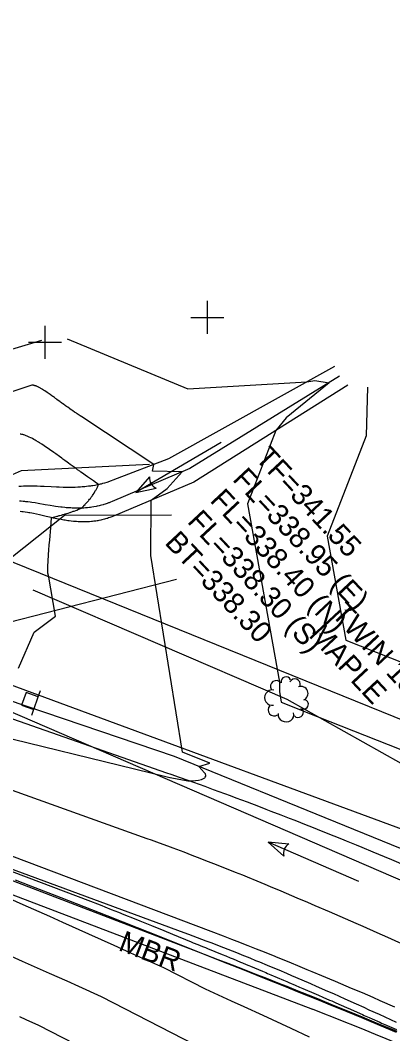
# Model space of a CAD drawing. Extents: x 487096 to 489566, y 221939 to 224454.
# Drawn here: x 488220.2 to 488276.8, y 223618.2 to 223772 of the extents above; entities that cross this region are included whole.
import ezdxf

# ---------------------------------------------------------------- set-up
doc = ezdxf.new("R2010")
doc.units = 0
for name, color, linetype in [('SV_BKLN_BKLN', 7, 'Continuous'), ('SV_DRAN_DRAN_TX', 7, 'Continuous'), ('SV_GDRL_GDRL_TX', 7, 'Continuous'), ('SV_GDRL_GR', 7, 'Continuous'), ('SV_MISC_MISC_TOPO', 7, 'Continuous'), ('SV_PIPE_CM_15', 7, 'Continuous'), ('SV_PIPE_FLOW', 7, 'Continuous'), ('SV_ROAD_BITRD', 7, 'Continuous'), ('SV_ROWL_HWYLOC', 7, 'Continuous'), ('SV_SIGN_SIGN', 7, 'Continuous'), ('SV_SURF_INDEX_CONTOUR', 7, 'Continuous'), ('SV_SURF_INTER_CONTOUR', 7, 'Continuous'), ('SV_SURF_SPOT', 7, 'Continuous'), ('SV_TRAF_PVMTL', 7, 'Continuous'), ('SV_TREE_TREELN', 7, 'Continuous'), ('SV_TREE_TREEVEG', 7, 'Continuous'), ('SV_TREE_TREEVEG_TX', 7, 'Continuous'), ('SV_UTOH_OVERHEAD_LINES', 7, 'Continuous'), ('SV_WATR_INWETF', 7, 'Continuous'), ('SV_WATR_STREAM', 7, 'Continuous')]:
    doc.layers.add(name, color=color, linetype=linetype)

msp = doc.modelspace()

# ---------------------------------------------------------------- linework, layer by layer
at = {"layer": 'SV_BKLN_BKLN'}
for points in [[(488268.72, 223718), (488246, 223704.02), (488234.18, 223698.97), (488233.93, 223698.86), (488233.76, 223698.8), (488233.65, 223698.76), (488233.43, 223698.68), (488233.26, 223698.62), (488233.15, 223698.58), (488232.93, 223698.51), (488232.82, 223698.48), (488232.59, 223698.42), (488232.37, 223698.36), (488232.22, 223698.32), (488231.93, 223698.26), (488231.76, 223698.22), (488231.43, 223698.16), (488231.1, 223698.11), (488230.88, 223698.08), (488230.74, 223698.06), (488230.45, 223698.03), (488230.12, 223698), (488229.9, 223697.99), (488229.76, 223697.98), (488229.47, 223697.97), (488229.25, 223697.97), (488229.11, 223697.97), (488228.82, 223697.97), (488228.68, 223697.97), (488228.39, 223697.98), (488228.11, 223697.99), (488227.92, 223698), (488227.55, 223698.02), (488227.23, 223698.05), (488227.02, 223698.07), (488226.61, 223698.11), (488226.4, 223698.14), (488225.99, 223698.19), (488225.58, 223698.25), (488225.31, 223698.29), (488224.78, 223698.37), (488224, 223698.5), (488222.97, 223698.68), (488222.48, 223698.76), (488221.99, 223698.83), (488221.75, 223698.87), (488221.39, 223698.92), (488221.07, 223698.95), (488220.92, 223698.97), (488220.69, 223698.99), (488220.35, 223699.02), (488220.13, 223699.03)], [(488277.34, 223618.4), (488274.85, 223619.44), (488273.18, 223620.14), (488272.07, 223620.59), (488269.85, 223621.51), (488267.35, 223622.53), (488265.69, 223623.21), (488262.35, 223624.56), (488260.68, 223625.24), (488257.34, 223626.58), (488253.99, 223627.92), (488251.76, 223628.81), (488247.3, 223630.58), (488241.13, 223633.03), (488238.05, 223634.25), (488233.41, 223636.07), (488228.78, 223637.89), (488226.46, 223638.8), (488221.82, 223640.61), (488219.5, 223641.51)]]:
    msp.add_lwpolyline(points, dxfattribs=at)
at = {"layer": 'SV_DRAN_DRAN_TX'}
msp.add_line((488243.95, 223687.13), (488198.45, 223675.49), dxfattribs=at)
at = {"layer": 'SV_GDRL_GR'}
msp.add_lwpolyline([(488277.44, 223618.52), (488276.61, 223618.87), (488274.95, 223619.56), (488273.28, 223620.25), (488272.18, 223620.71), (488269.95, 223621.63), (488267.45, 223622.65), (488265.78, 223623.33), (488264.67, 223623.77), (488262.43, 223624.67), (488260.76, 223625.34), (488259.64, 223625.78), (488257.4, 223626.66), (488256.28, 223627.1), (488254.04, 223627.98), (488251.8, 223628.85), (488250.3, 223629.43), (488247.3, 223630.58), (488176.7, 223657.65), (488168.14, 223658.69), (488156.25, 223662.12)], dxfattribs=at)
at = {"layer": 'SV_MISC_MISC_TOPO'}
msp.add_line((488247.47, 223631.33), (488247.47, 223631.33), dxfattribs=at)
at = {"layer": 'SV_PIPE_CM_15'}
msp.add_lwpolyline([(488383.93, 223595.7), (488200.04, 223675.13)], dxfattribs=at)
at = {"layer": 'SV_PIPE_FLOW'}
for p, q in [((488250.72, 223707.96), (488237.8, 223700.34)), ((488239.88, 223702.73), (488237.8, 223700.34)), ((488237.8, 223700.34), (488240.89, 223701)), ((488271.65, 223641.32), (488257.88, 223647.26)), ((488257.88, 223647.26), (488260.23, 223645.15)), ((488261.03, 223646.99), (488257.88, 223647.26))]:
    msp.add_line(p, q, dxfattribs=at)
for centre, start, end in [((488241.5, 223702.53), 172.9205, 248.1221), ((488261.82, 223645.56), 119.0376, 194.2393)]:
    msp.add_arc(centre, 1.64, start, end, dxfattribs=at)
at = {"layer": 'SV_ROAD_BITRD'}
for points in [[(488295.35, 223639.2), (488243.64, 223660.28), (488207.07, 223672.67)], [(488277.35, 223619.89), (488275.62, 223620.69), (488274.75, 223621.09), (488273.22, 223621.79), (488272.45, 223622.15), (488271.29, 223622.67), (488269.56, 223623.45), (488267.82, 223624.23), (488266.95, 223624.61), (488265.21, 223625.38), (488264.34, 223625.76), (488263.03, 223626.33), (488261.47, 223627), (488260.69, 223627.33), (488259.53, 223627.82), (488258.36, 223628.31), (488257.77, 223628.55), (488256.6, 223629.04), (488256.01, 223629.28), (488255.13, 223629.64), (488253.95, 223630.12), (488253.36, 223630.35), (488252.48, 223630.7), (488251.15, 223631.23), (488249.97, 223631.69), (488249.37, 223631.92), (488248.48, 223632.26), (488247.15, 223632.77), (488245.81, 223633.27), (488245.14, 223633.51), (488178.96, 223657.88)]]:
    msp.add_lwpolyline(points, dxfattribs=at)
at = {"layer": 'SV_ROWL_HWYLOC'}
for points in [[(487756.92, 223854.03), (487819.74, 223823.93), (487982.51, 223759.36), (488009.69, 223754.74), (488041.14, 223750.63), (488071.96, 223735.45), (488100.92, 223722.74), (488124.66, 223715.6), (488155.68, 223709.25), (488178.9, 223706.07), (488296.16, 223658.56), (488379.4, 223617.17), (488410.15, 223595.68), (488443.8, 223549.21), (488472.24, 223469.86), (488477.06, 223418.16), (488475.62, 223352.08), (488474.08, 223317.48), (488463.17, 223231.25), (488461.58, 223189.46)], [(487750.08, 223817.31), (487833.81, 223784.33), (487880.61, 223763.01), (487930.05, 223747.42), (487951.57, 223737.03), (487996.66, 223715.69), (488020.23, 223704.76), (488056.94, 223694.06), (488093.65, 223683.37), (488127.21, 223671.39), (488156.25, 223662.12), (488168.14, 223658.69), (488264.6, 223621.9)]]:
    msp.add_lwpolyline(points, dxfattribs=at)
msp.add_arc((488082.83, 223151.77), 504.05, 56.3623, 68.8615, dxfattribs=at)
at = {"layer": 'SV_SIGN_SIGN'}
for p, q in [((488222.97, 223669.31), (488223.31, 223670.28)), ((488221.98, 223666.53), (488222.31, 223667.45))]:
    msp.add_line(p, q, dxfattribs=at)
msp.add_lwpolyline([(488222.29, 223667.43), (488222.96, 223669.32), (488221.11, 223669.98), (488220.43, 223668.09)], close=True, dxfattribs=at)
at = {"layer": 'SV_SURF_INDEX_CONTOUR'}
msp.add_lwpolyline([(488196.14, 223642.96), (488198.31, 223642.06), (488207.61, 223634.91), (488209.83, 223633.95), (488211.3, 223633.31), (488212.27, 223632.89), (488214.2, 223632.04), (488216.34, 223631.1), (488217.75, 223630.47), (488220.54, 223629.23), (488221.91, 223628.62), (488224.63, 223627.4), (488227.31, 223626.2), (488229.06, 223625.41), (488232.53, 223623.85), (488250.32, 223614.68)], dxfattribs=at)
at = {"layer": 'SV_SURF_INTER_CONTOUR'}
for points in [[(488223.46, 223723.45), (488178.62, 223709.99), (488178.12, 223709.92), (488177.51, 223709.86), (488156.06, 223710.21), (488154.95, 223709.99), (488152.78, 223709.84), (488137.33, 223707.09), (488132.77, 223701.96), (488101.76, 223708.87)], [(488227.38, 223723.67), (488245.66, 223716.07), (488263.72, 223717.15), (488264.94, 223717.38), (488267.13, 223717.02), (488260.62, 223711.71), (488259.04, 223709.75), (488254.73, 223698.61), (488259.59, 223671.55), (488259.58, 223670.15), (488259.84, 223668.53), (488265.33, 223666.37), (488290.74, 223656.31)], [(488212.07, 223664.63), (488242.33, 223657.26), (488242.97, 223657.11), (488243, 223657.1), (488244.31, 223656.83), (488244.34, 223656.82), (488245.7, 223656.59), (488245.71, 223656.59), (488245.93, 223656.56), (488246.4, 223656.57), (488247.32, 223656.67), (488247.76, 223656.78), (488247.97, 223656.86), (488248.24, 223657.04), (488248.32, 223657.13), (488248.39, 223657.3), (488248.39, 223657.46), (488248.36, 223657.55), (488248.34, 223657.62), (488248.27, 223657.73), (488248.21, 223657.82), (488248.17, 223657.87), (488248.08, 223657.97), (488248.03, 223658.02), (488247.94, 223658.1), (488247.85, 223658.18), (488247.79, 223658.23), (488247.37, 223658.76), (488249.04, 223659.27), (488244.87, 223660.91), (488240.04, 223690.79), (488240.11, 223699.19), (488242.54, 223700.96), (488244.8, 223703.51), (488240.29, 223703.61), (488240.5, 223704.6), (488229.56, 223711.84), (488229.33, 223712), (488229.18, 223712.1), (488228.9, 223712.29), (488228.76, 223712.38), (488228.49, 223712.56), (488228.24, 223712.73), (488228.08, 223712.84), (488227.98, 223712.92), (488227.77, 223713.06), (488227.66, 223713.14), (488227.45, 223713.29), (488227.24, 223713.43), (488227.11, 223713.53), (488227.02, 223713.59), (488226.85, 223713.71), (488226.67, 223713.84), (488226.55, 223713.92), (488226.48, 223713.98), (488226.33, 223714.09), (488226.22, 223714.17), (488226, 223714.32), (488225.8, 223714.47), (488225.67, 223714.57), (488225.58, 223714.63), (488225.42, 223714.75), (488225.28, 223714.85), (488225.19, 223714.91), (488225.02, 223715.04), (488224.78, 223715.21), (488224.62, 223715.32), (488224.32, 223715.53), (488223.96, 223715.78), (488223.78, 223715.9), (488223.62, 223716), (488223.54, 223716.05), (488223.38, 223716.15), (488223.31, 223716.19), (488223.2, 223716.25), (488223.1, 223716.3), (488223.06, 223716.33), (488222.99, 223716.36), (488222.89, 223716.41), (488222.79, 223716.46), (488222.74, 223716.48), (488222.66, 223716.51), (488222.62, 223716.52), (488222.56, 223716.55), (488222.5, 223716.57), (488222.47, 223716.57), (488222.42, 223716.59), (488222.39, 223716.6), (488222.35, 223716.61), (488222.29, 223716.62), (488222.27, 223716.62), (488222.23, 223716.63), (488222.17, 223716.64), (488222.12, 223716.64), (488222.09, 223716.64), (488222.06, 223716.64), (488222.02, 223716.64), (488222, 223716.64), (488221.97, 223716.64), (488212.33, 223713.46)], [(488272.95, 223716.32), (488272.73, 223708.95), (488266.83, 223693.72), (488269.67, 223677.92), (488285.67, 223671.59)], [(488219.97, 223673.69), (488222.34, 223679.13), (488225.57, 223681.56), (488224.52, 223687.82), (488224.51, 223687.83), (488224.5, 223687.84), (488224.49, 223687.86), (488224.49, 223687.87), (488224.48, 223687.9), (488224.47, 223687.92), (488224.47, 223687.94), (488224.46, 223687.99), (488224.45, 223688.01), (488224.45, 223688.03), (488224.44, 223688.07), (488224.43, 223688.14), (488224.43, 223688.19), (488224.42, 223688.22), (488224.42, 223688.3), (488224.42, 223688.39), (488224.41, 223688.46), (488224.41, 223688.51), (488224.41, 223688.61), (488224.41, 223688.7), (488224.41, 223688.76), (488224.41, 223688.89), (488224.42, 223688.96), (488224.42, 223689.12), (488224.43, 223689.29), (488224.43, 223689.41), (488224.45, 223689.7), (488224.47, 223689.97), (488224.48, 223690.18), (488224.51, 223690.65), (488224.53, 223690.93), (488224.58, 223691.59), (488224.65, 223692.43), (488224.71, 223693.12), (488224.87, 223695.02), (488225, 223696.53), (488225.29, 223696.61), (488225.31, 223696.61), (488225.35, 223696.62), (488225.84, 223696.75), (488225.94, 223696.78), (488226.16, 223696.84), (488226.23, 223696.86), (488226.51, 223696.93), (488226.69, 223696.99), (488226.93, 223697.06), (488227.04, 223697.09), (488227.14, 223697.12), (488227.33, 223697.18), (488227.51, 223697.23), (488227.76, 223697.32), (488227.83, 223697.34), (488227.93, 223697.37), (488228.07, 223697.42), (488228.29, 223697.5), (488228.38, 223697.53), (488228.42, 223697.54), (488228.65, 223697.63), (488228.69, 223697.64), (488228.82, 223697.69), (488229.08, 223697.8), (488229.1, 223697.81), (488229.11, 223697.81), (488229.25, 223697.86), (488229.26, 223697.87), (488229.47, 223697.96), (488229.47, 223697.96), (488229.51, 223697.97), (488229.73, 223698.18), (488229.75, 223698.2), (488229.87, 223698.32), (488229.9, 223698.36), (488230.08, 223698.53), (488230.11, 223698.57), (488230.35, 223698.81), (488230.4, 223698.88), (488230.59, 223699.08), (488230.67, 223699.17), (488230.77, 223699.32), (488230.89, 223699.45), (488231, 223699.62), (488231.15, 223699.8), (488231.21, 223699.9), (488231.33, 223700.05), (488231.44, 223700.23), (488231.48, 223700.29), (488231.66, 223700.64), (488231.73, 223700.71), (488231.75, 223700.75), (488231.95, 223701.17), (488231.97, 223701.2), (488231.99, 223701.22), (488232.09, 223701.46), (488232.09, 223701.46), (488232.12, 223701.55), (488232.04, 223701.61), (488231.8, 223701.78), (488231.35, 223702.1), (488230.91, 223702.41), (488230.62, 223702.61), (488230.44, 223702.74), (488230.08, 223703), (488229.69, 223703.28), (488229.44, 223703.46), (488229.27, 223703.58), (488228.95, 223703.81), (488228.72, 223703.98), (488228.26, 223704.31), (488227.83, 223704.62), (488227.55, 223704.83), (488227.37, 223704.96), (488227.01, 223705.22), (488226.72, 223705.43), (488226.53, 223705.56), (488226.17, 223705.83), (488225.64, 223706.21), (488225.31, 223706.44), (488224.68, 223706.89), (488223.89, 223707.43), (488223.53, 223707.67), (488223.18, 223707.89), (488223, 223708), (488222.67, 223708.2), (488222.51, 223708.29), (488222.28, 223708.42), (488222.08, 223708.53), (488221.98, 223708.59), (488221.83, 223708.66), (488221.61, 223708.77), (488221.41, 223708.86), (488221.3, 223708.9), (488221.13, 223708.97), (488221.04, 223709.01), (488220.91, 223709.05), (488220.79, 223709.09), (488220.73, 223709.11), (488220.61, 223709.15), (488220.55, 223709.16), (488220.46, 223709.18), (488220.34, 223709.21), (488220.28, 223709.22), (488220.2, 223709.23)], [(488185.76, 223655.38), (488230.92, 223638.31), (488231.94, 223637.91), (488232.63, 223637.64), (488233.1, 223637.45), (488234.06, 223637.07), (488235.17, 223636.62), (488235.94, 223636.31), (488237.55, 223635.66), (488238.39, 223635.32), (488240.15, 223634.6), (488242.02, 223633.84), (488243.34, 223633.29), (488246.16, 223632.13), (488246.51, 223632), (488247.22, 223631.72), (488247.91, 223631.45), (488248.36, 223631.27), (488248.66, 223631.15), (488250.87, 223630.23), (488251.46, 223629.99), (488252.11, 223629.73), (488252.54, 223629.55), (488253.69, 223629.07), (488253.97, 223628.96), (488254.53, 223628.72), (488254.93, 223628.55), (488255.2, 223628.44), (488257, 223627.69), (488257.53, 223627.46), (488257.79, 223627.35), (488258.3, 223627.13), (488260.19, 223626.34), (488260.69, 223626.12), (488261.01, 223625.98), (488261.99, 223625.57), (488262.63, 223625.28), (488263.15, 223625.05), (488265.16, 223624.2), (488265.5, 223624.05), (488266.17, 223623.74), (488267.2, 223623.3), (488267.52, 223623.16), (488268.15, 223622.87), (488269.75, 223622.18), (488270.35, 223621.91), (488271.82, 223621.28), (488272.19, 223621.1), (488272.44, 223620.98), (488273.19, 223620.66), (488273.67, 223620.43), (488274.82, 223619.94), (488275.07, 223619.81), (488275.57, 223619.57), (488277.34, 223618.81)], [(488264.16, 223617.65), (488261.36, 223618.97), (488259.95, 223619.63), (488257.1, 223620.95), (488254.22, 223622.27), (488252.29, 223623.15), (488248.38, 223624.93), (488242.05, 223628.19), (488237.04, 223630.44), (488234.5, 223631.59), (488230.63, 223633.32), (488226.7, 223635.09), (488224.71, 223635.97), (488220.68, 223637.77), (488218.64, 223638.67)], [(488220.11, 223620.81), (488221.09, 223620.37), (488223.01, 223619.51), (488252.27, 223604.44)]]:
    msp.add_lwpolyline(points, dxfattribs=at)
at = {"layer": 'SV_SURF_SPOT'}
for p, q in [((488248.65, 223724.44), (488248.65, 223729.44)), ((488246.15, 223726.94), (488251.15, 223726.94)), ((488248.65, 223726.94), (488248.65, 223726.94)), ((488224.01, 223720.65), (488224.01, 223725.65)), ((488221.51, 223723.15), (488226.51, 223723.15)), ((488224.01, 223723.15), (488224.01, 223723.15))]:
    msp.add_line(p, q, dxfattribs=at)
at = {"layer": 'SV_TRAF_PVMTL'}
for points in [[(488277.08, 223622.24), (488274.9, 223623.19), (488273.81, 223623.67), (488272.17, 223624.38), (488270.53, 223625.08), (488269.71, 223625.43), (488268.07, 223626.13), (488267.25, 223626.48), (488266.01, 223627), (488264.55, 223627.61), (488263.81, 223627.91), (488262.71, 223628.37), (488261.06, 223629.05), (488259.4, 223629.72), (488258.57, 223630.05), (488256.91, 223630.72), (488256.08, 223631.05), (488254.84, 223631.54), (488253.17, 223632.19), (488252.34, 223632.51), (488251.08, 223632.99), (488249.2, 223633.71), (488179.96, 223659.88), (488023.17, 223716.7)], [(488279.28, 223631.34), (488276.05, 223632.78), (488274.44, 223633.5), (488272.29, 223634.45), (488271.21, 223634.93), (488269.59, 223635.64), (488267.16, 223636.7), (488265, 223637.63), (488263.92, 223638.1), (488262.3, 223638.79), (488260.67, 223639.48), (488259.86, 223639.82), (488258.23, 223640.51), (488257.41, 223640.84), (488256.19, 223641.35), (488254.74, 223641.94), (488254.01, 223642.24), (488252.92, 223642.68), (488251.28, 223643.34), (488249.64, 223643.99), (488248.82, 223644.31), (488247.17, 223644.95), (488246.35, 223645.26), (488245.11, 223645.73), (488244.01, 223646.15), (488243.46, 223646.36), (488242.63, 223646.66), (488241.38, 223647.12), (488240.14, 223647.57), (488239.51, 223647.8), (488153.72, 223678.52)], [(488278.87, 223643.63), (488276.63, 223644.58), (488275.51, 223645.05), (488273.82, 223645.75), (488272.14, 223646.45), (488271.29, 223646.8), (488269.79, 223647.41), (488269.04, 223647.72), (488267.91, 223648.18), (488266.22, 223648.86), (488264.52, 223649.53), (488263.68, 223649.87), (488261.98, 223650.54), (488261.13, 223650.87), (488259.85, 223651.37), (488258.34, 223651.95), (488257.58, 223652.24), (488256.44, 223652.68), (488254.73, 223653.32), (488253.02, 223653.97), (488252.16, 223654.28), (488250.45, 223654.92), (488249.59, 223655.23), (488248.3, 223655.7), (488246.58, 223656.32), (488245.72, 223656.63), (488244.43, 223657.09), (488243.13, 223657.55), (488242.49, 223657.77), (488197.68, 223673.45)]]:
    msp.add_lwpolyline(points, dxfattribs=at)
at = {"layer": 'SV_TREE_TREELN'}
msp.add_lwpolyline([(488222.16, 223685.58), (488260.7, 223668.96), (488292.44, 223651.19), (488333.36, 223632.41), (488374.4, 223610.79), (488410.05, 223595.83)], dxfattribs=at)
at = {"layer": 'SV_TREE_TREEVEG'}
msp.add_line((488260.7, 223668.96), (488260.7, 223668.96), dxfattribs=at)
for centre, radius, start, end in [((488259.09, 223670.93), 0.874, 35.9933, 211.459), ((488260.59, 223671.62), 0.75, 23.2911, 192.3579), ((488261.91, 223671.2), 0.85, 345.5308, 152.7093), ((488262.87, 223669.85), 1.06, 294.1859, 111.1082), ((488258.5, 223669.21), 1.17, 79.3292, 279.9889), ((488258.78, 223667.36), 0.922, 137.0157, 304.5501)]:
    msp.add_arc(centre, radius, start, end, dxfattribs=at)
for centre, major_axis, ratio, start_param, end_param in [((488263.16, 223668.2), (0.822, -0.013), 0.901056, 4.216583, 7.444153), ((488260.57, 223666.63), (-1.2, 0.16), 0.902156, 0, 3.5401), ((488262.42, 223667), (0.08, -0.798), 0.999752, 5.391582, 8.241319)]:
    msp.add_ellipse(centre, major_axis=major_axis, ratio=ratio, start_param=start_param, end_param=end_param, dxfattribs=at)
at = {"layer": 'SV_UTOH_OVERHEAD_LINES'}
msp.add_lwpolyline([(488477.01, 222631.44), (488424.13, 222778.25), (488391.68, 223012.96), (488449.87, 223205.72), (488470, 223438.33), (488349.56, 223622.89), (488159.18, 223693.12), (487993.17, 223755.78), (487804.2, 223830.22), (487742.26, 223860.21)], dxfattribs=at)
at = {"layer": 'SV_WATR_INWETF'}
for points in [[(488239.84, 223704.58), (488220.38, 223703.66), (488213.5, 223700.6), (488197.29, 223680.56)], [(488204, 223677.74), (488216.53, 223688.64), (488226.96, 223696.92), (488243.2, 223696.98)]]:
    msp.add_lwpolyline(points, dxfattribs=at)
at = {"layer": 'SV_WATR_STREAM'}
for points in [[(488267.93, 223719.49), (488242.74, 223705.47), (488234.29, 223702.2), (488234.04, 223702.11), (488233.88, 223702.05), (488233.55, 223701.94), (488233.38, 223701.89), (488233.05, 223701.79), (488232.72, 223701.7), (488232.5, 223701.64), (488232.36, 223701.61), (488232.07, 223701.54), (488231.9, 223701.5), (488231.57, 223701.44), (488231.25, 223701.38), (488231.03, 223701.35), (488230.88, 223701.33), (488230.59, 223701.29), (488230.27, 223701.25), (488230.05, 223701.23), (488229.91, 223701.21), (488229.62, 223701.19), (488229.4, 223701.17), (488228.97, 223701.15), (488228.55, 223701.13), (488228.26, 223701.12), (488228.07, 223701.12), (488227.7, 223701.11), (488227.38, 223701.11), (488227.17, 223701.12), (488226.75, 223701.12), (488226.13, 223701.14), (488225.72, 223701.16), (488224.91, 223701.2), (488223.85, 223701.25), (488223.33, 223701.27), (488222.81, 223701.3), (488222.56, 223701.3), (488222.06, 223701.32), (488221.81, 223701.32), (488221.44, 223701.32), (488221.12, 223701.31), (488220.96, 223701.31), (488220.72, 223701.3), (488220.37, 223701.28), (488220.02, 223701.25)], [(488269.98, 223716.63), (488246.57, 223701.91), (488234.38, 223696.76), (488234.13, 223696.67), (488233.97, 223696.6), (488233.86, 223696.56), (488233.65, 223696.49), (488233.48, 223696.43), (488233.38, 223696.4), (488233.16, 223696.33), (488233.05, 223696.3), (488232.84, 223696.25), (488232.62, 223696.19), (488232.48, 223696.16), (488232.19, 223696.1), (488232.03, 223696.07), (488231.93, 223696.05), (488231.71, 223696.02), (488231.39, 223695.98), (488231.18, 223695.95), (488231.04, 223695.94), (488230.76, 223695.92), (488230.44, 223695.9), (488230.23, 223695.89), (488230.09, 223695.89), (488229.81, 223695.89), (488229.6, 223695.89), (488229.47, 223695.89), (488229.19, 223695.9), (488229.05, 223695.91), (488228.78, 223695.93), (488228.5, 223695.95), (488228.32, 223695.96), (488227.96, 223696), (488227.66, 223696.04), (488227.45, 223696.07), (488227.05, 223696.13), (488226.85, 223696.17), (488226.46, 223696.24), (488226.06, 223696.31), (488225.8, 223696.36), (488225.29, 223696.47), (488224.91, 223696.56), (488224.15, 223696.73), (488223.18, 223696.95), (488222.7, 223697.06), (488222.23, 223697.16), (488222, 223697.2), (488221.7, 223697.26), (488221.54, 223697.28), (488221.32, 223697.32), (488220.99, 223697.37), (488220.66, 223697.41), (488220.5, 223697.43), (488220.22, 223697.45)]]:
    msp.add_lwpolyline(points, dxfattribs=at)

# ---------------------------------------------------------------- texts
at = {"layer": 'SV_DRAN_DRAN_TX'}
for s, p in [('TF=341.55', (488255.77, 223705.47)), ('FL=338.95 (E)', (488252.33, 223702.26)), ('FL=338.40 (N)', (488248.9, 223699.06)), ('FL=338.30 (S)', (488245.46, 223695.85)), ('BT=338.30', (488242.03, 223692.64))]:
    msp.add_text(s, height=3.2, rotation=313.0386, dxfattribs=at).set_placement(p)
at = {"layer": 'SV_GDRL_GDRL_TX'}
msp.add_text('MBR', height=3.2, rotation=339.3252, dxfattribs=at).set_placement((488234.98, 223630.91))
at = {"layer": 'SV_TREE_TREEVEG_TX'}
for s, p in [('TWIN 15"', (488267.34, 223681.79)), ('MAPLE', (488263.9, 223678.58))]:
    msp.add_text(s, height=3.2, rotation=313.0386, dxfattribs=at).set_placement(p)

doc.saveas('drawing.dxf')
